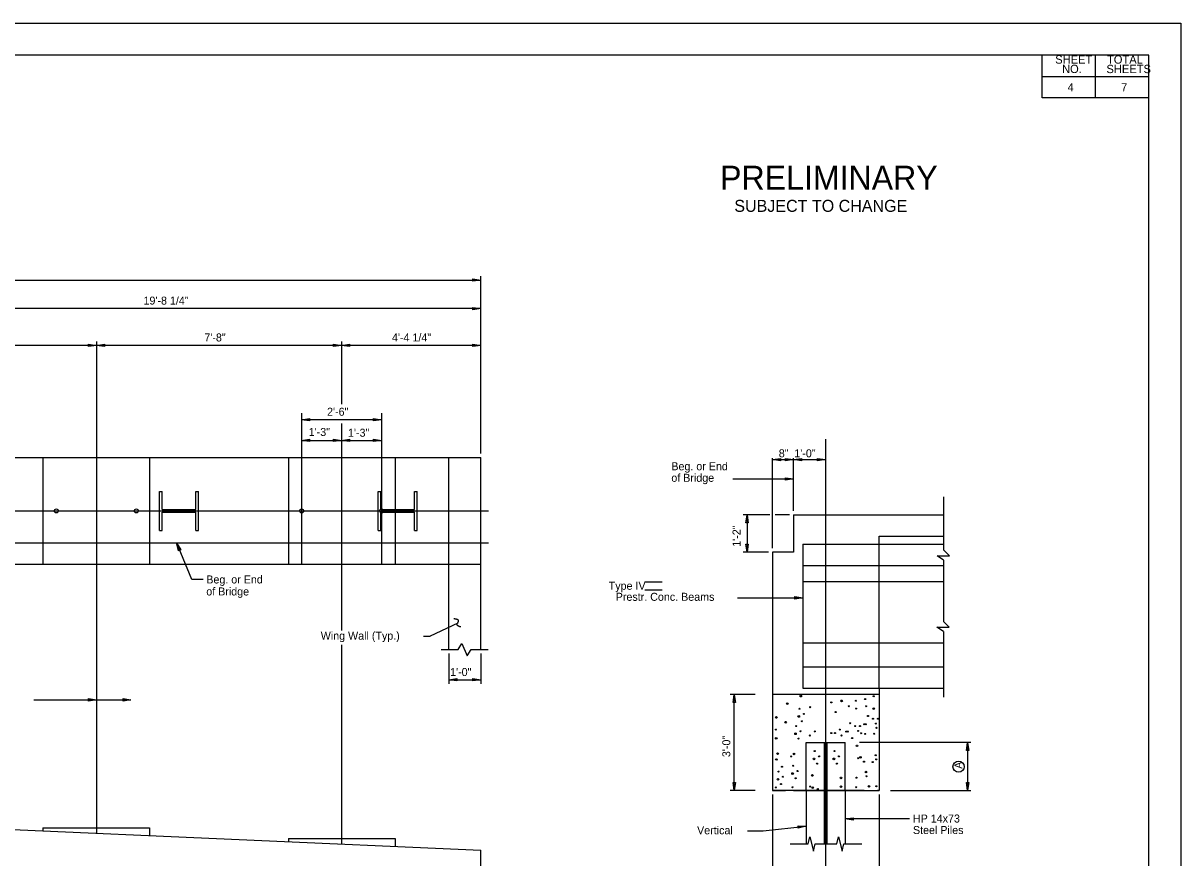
# Model space of a CAD drawing. Extents: x -470 to -397.8, y 402.4 to 446.4.
# Drawn here: x -434.18 to -398, y 420.31 to 446.38 of the extents above; entities that cross this region are included whole.
import ezdxf

# ---------------------------------------------------------------- set-up
doc = ezdxf.new("R2010")
doc.units = 0
for name, color, linetype in [('BR_AUTO DIMENSION', 7, 'Continuous'), ('BR_BORDER LINES', 7, 'Continuous'), ('BR_CENTER LINES', 7, 'Continuous'), ('BR_CONCRETE', 7, 'Continuous'), ('BR_PRESTRESSED BEAM', 7, 'Continuous'), ('BR_REBAR', 7, 'Continuous'), ('BR_STRUCTURAL STEEL', 7, 'Continuous'), ('BR_TEXT', 7, 'Continuous'), ('Default', 7, 'Continuous'), ('RD_SHT_IplotShp', 7, 'Continuous')]:
    doc.layers.add(name, color=color, linetype=linetype)

msp = doc.modelspace()

# ---------------------------------------------------------------- linework, layer by layer
at = {"layer": 'BR_AUTO DIMENSION'}
for p, q in [((-419.874, 432.942), (-419.874, 438.486)), ((-459.249, 438.361), (-419.874, 438.361)), ((-419.874, 437.468), (-439.561, 437.468)), ((-419.874, 432.942), (-419.874, 437.593)), ((-431.894, 436.317), (-439.561, 436.317)), ((-431.894, 436.442), (-431.894, 436.442)), ((-424.228, 436.317), (-431.894, 436.317)), ((-424.228, 436.442), (-424.228, 436.442)), ((-419.874, 436.317), (-424.228, 436.317)), ((-419.874, 432.942), (-419.874, 436.442)), ((-422.978, 433.997), (-425.478, 433.997)), ((-425.478, 433.354), (-422.978, 433.354)), ((-410.769, 429.989), (-410.769, 432.792)), ((-410.769, 432.753), (-409.103, 432.753)), ((-410.103, 431.155), (-410.103, 432.792)), ((-412.004, 432.15), (-410.103, 432.15)), ((-405.417, 431.59), (-405.417, 429.934)), ((-410.845, 431.03), (-411.686, 431.03)), ((-411.561, 431.03), (-411.561, 429.864)), ((-410.228, 431.03), (-410.681, 431.03)), ((-429.384, 430.15), (-428.925, 429.021)), ((-410.894, 429.864), (-411.686, 429.864)), ((-405.234, 429.748), (-405.417, 429.934)), ((-405.617, 429.748), (-405.234, 429.748)), ((-405.417, 429.612), (-405.617, 429.748)), ((-405.417, 429.612), (-405.417, 427.701)), ((-428.91, 429.021), (-428.558, 429.021)), ((-411.855, 428.436), (-409.82, 428.436)), ((-420.598, 427.643), (-421.46, 427.239)), ((-405.243, 427.524), (-405.417, 427.701)), ((-405.626, 427.524), (-405.243, 427.524)), ((-405.417, 427.382), (-405.626, 427.524)), ((-405.417, 427.382), (-405.417, 425.338)), ((-421.671, 427.239), (-421.46, 427.239)), ((-420.586, 426.817), (-420.472, 427.014)), ((-420.472, 427.014), (-420.309, 426.621)), ((-421.115, 426.817), (-420.586, 426.817)), ((-420.874, 426.692), (-420.874, 425.754)), ((-420.309, 426.621), (-420.183, 426.817)), ((-420.183, 426.817), (-419.654, 426.817)), ((-419.874, 426.692), (-419.874, 425.754)), ((-420.874, 425.879), (-419.874, 425.879)), ((-433.851, 425.249), (-430.812, 425.249)), ((-411.309, 425.416), (-412.082, 425.416)), ((-411.957, 422.416), (-411.957, 425.416)), ((-404.565, 423.916), (-408.041, 423.916)), ((-404.668, 423.916), (-404.668, 422.416)), ((-411.311, 422.416), (-412.082, 422.416)), ((-410.769, 422.291), (-410.769, 419.323)), ((-407.436, 422.291), (-407.436, 419.323)), ((-407.079, 422.416), (-404.566, 422.416)), ((-406.479, 421.532), (-408.493, 421.532)), ((-410.209, 420.748), (-409.65, 420.748)), ((-409.65, 420.748), (-409.594, 420.975)), ((-409.594, 420.975), (-409.483, 420.52)), ((-409.483, 420.52), (-409.427, 420.748)), ((-409.427, 420.748), (-408.757, 420.748)), ((-408.757, 420.748), (-408.701, 420.975)), ((-408.701, 420.975), (-408.589, 420.52)), ((-408.589, 420.52), (-408.534, 420.748)), ((-408.534, 420.748), (-407.976, 420.748))]:
    msp.add_line(p, q, dxfattribs=at)
for points in [[(-420.124, 438.399), (-419.874, 438.361), (-420.124, 438.324)], [(-420.124, 437.505), (-419.874, 437.468), (-420.124, 437.43)], [(-432.144, 436.355), (-431.894, 436.317), (-432.144, 436.28)], [(-431.644, 436.28), (-431.894, 436.317), (-431.644, 436.355)], [(-424.478, 436.355), (-424.228, 436.317), (-424.478, 436.28)], [(-423.978, 436.28), (-424.228, 436.317), (-423.978, 436.355)], [(-420.124, 436.355), (-419.874, 436.317), (-420.124, 436.28)], [(-425.228, 433.959), (-425.478, 433.997), (-425.228, 434.034)], [(-423.228, 434.034), (-422.978, 433.997), (-423.228, 433.959)], [(-425.228, 433.316), (-425.478, 433.354), (-425.228, 433.391)], [(-424.478, 433.391), (-424.228, 433.354), (-424.478, 433.316)], [(-423.978, 433.316), (-424.228, 433.354), (-423.978, 433.391)], [(-423.228, 433.391), (-422.978, 433.354), (-423.228, 433.316)], [(-410.519, 432.715), (-410.769, 432.753), (-410.519, 432.79)], [(-410.353, 432.79), (-410.103, 432.753), (-410.353, 432.715)], [(-409.853, 432.715), (-410.103, 432.753), (-409.853, 432.79)], [(-409.353, 432.79), (-409.103, 432.753), (-409.353, 432.715)], [(-410.353, 432.187), (-410.103, 432.15), (-410.353, 432.112)], [(-411.598, 430.78), (-411.561, 431.03), (-411.523, 430.78)], [(-429.328, 429.903), (-429.384, 430.15), (-429.251, 429.934)], [(-411.523, 430.114), (-411.561, 429.864), (-411.598, 430.114)], [(-410.064, 428.476), (-409.82, 428.436), (-410.064, 428.395)], [(-420.624, 425.842), (-420.874, 425.879), (-420.624, 425.917)], [(-420.124, 425.917), (-419.874, 425.879), (-420.124, 425.842)], [(-432.139, 425.29), (-431.894, 425.249), (-432.139, 425.209)], [(-431.056, 425.29), (-430.812, 425.249), (-431.056, 425.209)], [(-411.994, 425.166), (-411.957, 425.416), (-411.919, 425.166)], [(-404.706, 423.666), (-404.668, 423.916), (-404.631, 423.666)], [(-411.919, 422.666), (-411.957, 422.416), (-411.994, 422.666)], [(-404.631, 422.666), (-404.668, 422.416), (-404.706, 422.666)], [(-404.631, 422.666), (-404.668, 422.416), (-404.706, 422.666)], [(-408.243, 421.494), (-408.493, 421.532), (-408.243, 421.569)], [(-409.965, 421.314), (-409.712, 421.303), (-409.957, 421.239)]]:
    msp.add_lwpolyline(points, close=True, dxfattribs=at)
msp.add_lwpolyline([(-411.546, 421.16), (-411.057, 421.16), (-409.712, 421.303)], dxfattribs=at)
msp.add_open_spline([(-420.501, 427.525), (-420.677, 427.567), (-420.514, 427.762), (-420.724, 427.779)], degree=2, dxfattribs=at)
at = {"layer": 'BR_BORDER LINES'}
for p, q in [((-470.003, 446.383), (-398.003, 446.383)), ((-399.004, 445.38), (-466.337, 445.38)), ((-402.337, 444.047), (-402.337, 445.38)), ((-400.671, 445.38), (-400.671, 445.38)), ((-400.67, 444.047), (-400.67, 445.38)), ((-399.839, 445.38), (-399.839, 445.38)), ((-399.004, 403.38), (-399.004, 445.38)), ((-402.337, 444.721), (-399.004, 444.721)), ((-399.004, 444.047), (-402.337, 444.047)), ((-399.004, 443.052), (-399.004, 444.047)), ((-399.004, 428.953), (-399.004, 443.052))]:
    msp.add_line(p, q, dxfattribs=at)
at = {"layer": 'BR_CENTER LINES'}
msp.add_line((-409.103, 433.394), (-409.103, 419.225), dxfattribs=at)
for centre in [(-409.784, 424.809), (-408.152, 424.976), (-407.838, 425.05), (-409.845, 424.581), (-408.029, 424.429), (-407.899, 424.489), (-407.533, 424.508), (-407.511, 424.375), (-407.471, 424.657), (-410.659, 424.32), (-409.948, 424.04), (-409.887, 424.268), (-409.445, 424.262), (-408.663, 424.321), (-408.457, 424.26), (-408.091, 424.279), (-407.997, 424.206), (-410.653, 423.391), (-409.31, 423.484), (-408.689, 423.484), (-407.634, 423.305), (-407.521, 423.391), (-409.98, 423.026), (-409.371, 423.256), (-408.75, 423.256), (-410.499, 422.619), (-410.438, 422.847), (-410.041, 422.799)]:
    msp.add_circle(centre, 0.0161, dxfattribs=at)
for centre in [(-410.302, 425.131), (-409.881, 425.365), (-408.605, 425.213), (-410.644, 424.7), (-409.942, 424.73), (-407.602, 424.974), (-410.352, 424.551), (-410.648, 424.048), (-410.045, 424.19), (-408.125, 423.813), (-410.605, 423.569), (-410.091, 423.559), (-409.468, 423.406), (-408.846, 423.406), (-408.016, 423.453), (-410.138, 422.948), (-407.844, 422.995), (-410.595, 422.768), (-409.519, 422.887), (-408.626, 422.811), (-408.626, 422.537), (-407.747, 422.546), (-409.509, 422.508)]:
    msp.add_ellipse(centre, major_axis=(0, 0.0258), ratio=0.982387, dxfattribs=at)
at = {"layer": 'BR_CONCRETE'}
for p, q in [((-425.894, 432.817), (-425.894, 429.483)), ((-422.561, 432.817), (-422.561, 429.483)), ((-407.436, 425.614), (-407.436, 430.364)), ((-407.436, 425.416), (-410.769, 425.416)), ((-410.769, 425.416), (-410.769, 422.416)), ((-407.436, 425.416), (-407.436, 422.416)), ((-459.249, 422.29), (-419.874, 420.558)), ((-410.769, 422.416), (-410.355, 422.416)), ((-407.896, 422.416), (-410.769, 422.416)), ((-410.11, 422.416), (-407.436, 422.416)), ((-407.436, 422.416), (-407.485, 422.416)), ((-433.561, 421.254), (-430.228, 421.254)), ((-425.894, 420.916), (-425.894, 420.823)), ((-425.894, 420.916), (-422.561, 420.916)), ((-422.561, 420.916), (-422.561, 420.676))]:
    msp.add_line(p, q, dxfattribs=at)
at = {"layer": 'BR_PRESTRESSED BEAM'}
for p, q in [((-407.436, 430.364), (-405.417, 430.364)), ((-409.82, 430.114), (-407.436, 430.114)), ((-409.82, 430.114), (-409.82, 425.614)), ((-407.436, 430.114), (-405.417, 430.114)), ((-409.82, 429.447), (-407.436, 429.447)), ((-407.436, 429.447), (-405.417, 429.447)), ((-409.82, 428.947), (-407.436, 428.947)), ((-407.436, 428.947), (-405.417, 428.947)), ((-409.82, 427.03), (-407.436, 427.03)), ((-407.436, 427.03), (-405.417, 427.03)), ((-409.82, 426.28), (-407.436, 426.28)), ((-407.436, 426.28), (-405.417, 426.28)), ((-409.82, 425.614), (-407.436, 425.614)), ((-407.436, 425.614), (-405.417, 425.614))]:
    msp.add_line(p, q, dxfattribs=at)
at = {"layer": 'BR_REBAR'}
for p, q in [((-431.894, 436.442), (-431.894, 421.087)), ((-424.228, 436.442), (-424.228, 434.48)), ((-425.478, 434.204), (-425.478, 429.483)), ((-422.978, 434.204), (-422.978, 429.483)), ((-424.228, 433.876), (-424.228, 427.41)), ((-459.249, 432.817), (-419.874, 432.817)), ((-433.561, 432.817), (-433.561, 429.483)), ((-430.228, 432.817), (-430.228, 429.483)), ((-420.874, 426.817), (-420.874, 432.817)), ((-419.874, 426.817), (-419.874, 432.817)), ((-460.008, 431.15), (-419.64, 431.15)), ((-410.103, 431.03), (-405.417, 431.03)), ((-410.103, 431.03), (-410.103, 429.864)), ((-459.249, 430.15), (-419.64, 430.15)), ((-410.103, 429.864), (-410.769, 429.864)), ((-410.769, 429.864), (-410.769, 425.416)), ((-458.249, 429.483), (-420.874, 429.483)), ((-458.249, 429.483), (-420.874, 429.483)), ((-420.874, 429.483), (-419.874, 429.483)), ((-424.228, 426.967), (-424.228, 420.75)), ((-407.436, 425.614), (-407.436, 425.416)), ((-409.144, 422.416), (-409.144, 423.916)), ((-409.061, 422.416), (-409.061, 423.916)), ((-409.144, 420.748), (-409.144, 422.416)), ((-409.061, 420.748), (-409.061, 422.416)), ((-433.561, 421.254), (-433.561, 421.16)), ((-430.228, 421.254), (-430.228, 421.014)), ((-419.874, 417.558), (-419.874, 420.558))]:
    msp.add_line(p, q, dxfattribs=at)
for centre in [(-433.144, 431.15), (-430.644, 431.15), (-425.478, 431.15), (-422.978, 431.15)]:
    msp.add_circle(centre, 0.0625, dxfattribs=at)
msp.add_ellipse((-407.829, 422.863), major_axis=(0.0177, 0), ratio=0.9167, dxfattribs=at)
at = {"layer": 'BR_STRUCTURAL STEEL'}
for p, q in [((-429.92, 431.758), (-429.837, 431.758)), ((-429.92, 430.542), (-429.92, 431.758)), ((-429.837, 431.192), (-429.837, 431.758)), ((-428.788, 431.758), (-428.704, 431.758)), ((-428.787, 431.192), (-428.788, 431.758)), ((-428.702, 430.542), (-428.704, 431.758)), ((-423.087, 431.758), (-423.003, 431.758)), ((-423.087, 430.542), (-423.087, 431.758)), ((-423.003, 431.192), (-423.003, 431.758)), ((-421.954, 431.758), (-421.87, 431.758)), ((-421.953, 431.192), (-421.954, 431.758)), ((-421.868, 430.542), (-421.868, 431.758)), ((-421.868, 430.542), (-421.868, 431.758)), ((-429.837, 431.192), (-428.787, 431.192)), ((-429.837, 430.542), (-429.837, 431.108)), ((-429.837, 431.108), (-428.786, 431.108)), ((-428.785, 430.542), (-428.786, 431.108)), ((-423.003, 431.192), (-421.953, 431.192)), ((-423.003, 430.542), (-423.003, 431.108)), ((-423.003, 431.108), (-421.953, 431.108)), ((-421.952, 430.542), (-421.953, 431.108)), ((-429.92, 430.542), (-429.837, 430.542)), ((-428.785, 430.542), (-428.702, 430.542)), ((-423.087, 430.542), (-423.003, 430.542)), ((-421.952, 430.542), (-421.868, 430.542)), ((-409.712, 422.416), (-409.712, 423.916)), ((-409.712, 423.916), (-408.493, 423.916)), ((-408.493, 422.416), (-408.493, 423.916)), ((-409.712, 422.416), (-408.493, 422.416)), ((-409.712, 422.416), (-409.712, 420.748)), ((-408.493, 422.416), (-408.493, 420.748))]:
    msp.add_line(p, q, dxfattribs=at)
at = {"layer": 'BR_TEXT'}
for p, q in [((-414.757, 428.937), (-414.217, 428.937)), ((-414.756, 428.687), (-414.215, 428.687))]:
    msp.add_line(p, q, dxfattribs=at)
msp.add_circle((-404.949, 423.162), 0.175, dxfattribs=at)
at = {"layer": 'Default'}
msp.add_line((-409.103, 425.481), (-409.103, 425.481), dxfattribs=at)
for centre, major_axis in [((-408.926, 425.167), (0.0177, 0)), ((-408.606, 425.224), (-0.0177, 0)), ((-408.157, 425.222), (0.0177, 0)), ((-407.87, 425.275), (0.0177, 0)), ((-407.601, 425.362), (0.0177, 0)), ((-409.92, 424.972), (0.0177, 0)), ((-409.585, 425.02), (-0.0177, 0)), ((-408.792, 424.867), (0.0177, 0)), ((-408.378, 425.048), (-0.0177, 0)), ((-407.778, 424.745), (0.0177, 0)), ((-410.023, 424.431), (0.0177, 0)), ((-408.336, 424.517), (0.0177, 0)), ((-408.182, 424.431), (-0.0177, 0)), ((-407.851, 424.487), (0.0177, 0)), ((-407.624, 424.66), (-0.0177, 0)), ((-409.599, 424.136), (0.0177, 0)), ((-408.926, 424.211), (0.0177, 0)), ((-408.812, 424.212), (0.0177, 0)), ((-408.606, 424.136), (-0.0177, 0)), ((-408.409, 424.259), (0.0177, 0)), ((-408.274, 424.057), (0.0177, 0)), ((-407.87, 424.187), (0.0177, 0)), ((-407.585, 424.19), (0.0177, 0)), ((-409.446, 423.647), (0.0177, 0)), ((-408.825, 423.647), (0.0177, 0)), ((-410.629, 423.385), (0.0177, 0)), ((-410.179, 423.481), (0.0177, 0)), ((-408.087, 423.424), (0.0177, 0)), ((-407.906, 423.318), (0.0177, 0)), ((-407.539, 423.519), (0.0177, 0)), ((-410.574, 423.01), (0.0177, 0)), ((-410.468, 423.158), (0.0177, 0)), ((-410.116, 423.19), (0.0177, 0)), ((-409.588, 422.54), (0.0177, 0)), ((-408.142, 422.818), (0.0177, 0)), ((-407.518, 422.55), (0.0177, 0)), ((-410.66, 422.515), (0.0177, 0)), ((-410.137, 422.521), (0.0177, 0)), ((-409.35, 422.464), (0.0177, 0)), ((-408.15, 422.521), (0.0177, 0))]:
    msp.add_ellipse(centre, major_axis=major_axis, ratio=0.9167, dxfattribs=at)
at = {"layer": 'RD_SHT_IplotShp'}
for p, q in [((-470.003, 446.38), (-398.003, 446.38)), ((-398.003, 446.38), (-398.003, 402.38))]:
    msp.add_line(p, q, dxfattribs=at)

# ---------------------------------------------------------------- texts
at = {"layer": 'BR_CONCRETE'}
for s, height, p in [('PRELIMINARY', 0.75, (-412.401, 441.18)), ('SUBJECT TO CHANGE', 0.375, (-411.957, 440.49))]:
    msp.add_text(s, height=height, dxfattribs=at).set_placement(p)
at = {"layer": 'BR_TEXT'}
for s, height, p in [('SHEET', 0.26, (-401.929, 445.119)), ('TOTAL', 0.26, (-400.311, 445.118)), ('NO.', 0.26, (-401.716, 444.825)), ('SHEETS', 0.26, (-400.329, 444.823)), ('4', 0.25, (-401.54, 444.258)), ('7', 0.25, (-399.866, 444.258)), ('19\'-8 1/4"', 0.25, (-430.42, 437.593)), ('7\'-8"', 0.25, (-428.518, 436.442)), ('4\'-4 1/4"', 0.25, (-422.655, 436.442)), ('2\'-6"', 0.25, (-424.684, 434.122)), ('1\'-3"', 0.25, (-425.258, 433.49)), ('1\'-3"', 0.25, (-424.03, 433.466)), ('8"', 0.25, (-410.568, 432.824)), ('1\'-0"', 0.25, (-410.082, 432.824)), ('Beg. or End', 0.25, (-413.925, 432.419)), ('of Bridge', 0.25, (-413.925, 432.059)), ('Beg. or End ', 0.25, (-428.458, 428.884)), ('of Bridge', 0.25, (-428.458, 428.509)), ('  Type IV', 0.25, (-416.068, 428.687)), ('Prestr. Conc. Beams', 0.25, (-415.663, 428.342)), ('Wing Wall (Typ.)', 0.25, (-424.882, 427.127)), ('1\'-0"', 0.25, (-420.839, 425.993)), ('HP 14x73', 0.25, (-406.375, 421.418)), ('Vertical', 0.25, (-413.121, 421.051)), ('Steel Piles', 0.25, (-406.375, 421.058))]:
    msp.add_text(s, height=height, dxfattribs=at).set_placement(p)
for s, p in [('1\'-2"', (-411.763, 430.03)), ('3\'-0"', (-412.082, 423.46)), ('A', (-404.827, 423.094))]:
    msp.add_text(s, height=0.25, rotation=90, dxfattribs=at).set_placement(p)

doc.saveas('drawing.dxf')
